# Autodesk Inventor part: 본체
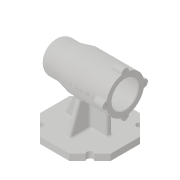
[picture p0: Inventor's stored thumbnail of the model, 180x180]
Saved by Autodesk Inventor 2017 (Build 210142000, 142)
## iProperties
Created: 2019-12
Part Number: 본체
Material: Generic
Document SubType Name: Modeling
Designer: 5-14-le
Density: 1 g/cm^3
Appearance: Default
Author: 5-14-le
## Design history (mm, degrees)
sketch "스케치2" dims "d0" = 112
  geometry: L1 (-23.196, -56)-(-56, -23.196); L2 (-56, -23.196)-(-56, 23.196); L3 (-56, 23.196)-(-23.196, 56); L4 (-23.196, 56)-(23.196, 56); L5 (23.196, 56)-(56, 23.196); L6 (56, 23.196)-(56, -23.196); L7 (56, -23.196)-(23.196, -56); L8 (23.196, -56)-(-23.196, -56); L9 (78.4, 0)-(-78.4, 0) reference; 4 further points
  constraints: 16 end point, 2 coincident, 1 midpoint, 1 parallel, 1 vertical alignment, 19 other
extrude "돌출1" new body sketch "스케치2" distance "d1" = 10; taper "d2" = 0 deg
sketch "스케치3"
  geometry: L1 (56, 23.196)-(23.196, 56) reference; L2 (-23.196, 56)-(-56, 23.196) reference; L3 (-56, -23.196)-(-23.196, -56) reference; L4 (23.196, -56)-(56, -23.196) reference; L5 (-39.598, 39.598)-(39.598, -39.598); L6 (39.598, 39.598)-(-39.598, -39.598); L7 (-78.4, 0)-(78.4, 0) reference; C1 r 5 at (-39.598, 39.598); C2 r 5 at (39.598, 39.598); C3 r 5 at (39.598, -39.598); C4 r 5 at (-39.598, -39.598); 1 further point
  constraints: 4 centre point, 4 coincident, 4 end point, 4 midpoint, 3 equal radius
  dimensions: "d3" = 10 diameter of C1
extrude "돌출2" cut sketch "스케치3" stored distance "d4" = 10; taper "d5" = 0 deg
sketch "스케치4"
  geometry: L1 (56, 80)-(-56, 80); L2 (-56, 80)-(-56, 105); L3 (56, 110)-(56, 80); L4 (56, 110)-(-11, 110); L5 (-11, 110)-(-31, 105); L6 (-31, 105)-(-56, 105); L7 (-23.196, 0)-(23.196, 0) reference; L8 (56, 0)-(56, 10) reference; L9 (56, 101)-(41, 101); L10 (41, 101)-(41, 104); L11 (41, 104)-(-13, 104); L12 (-13, 104)-(-13, 101); L13 (-13, 101)-(-25, 101); L14 (-25, 101)-(-25, 97.5); L15 (-25, 97.5)-(-43, 97.5); L16 (-43, 97.5)-(-43, 96); L17 (-43, 96)-(-47, 96); L18 (-47, 96)-(-47, 90.5); L19 (-47, 90.5)-(-50, 90.5); L20 (-50, 90.5)-(-50, 80); 1 further point
  constraints: 36 end point, 12 perpendicular, 4 point on line, 3 horizontal, 1 collinear, 1 parallel
  dimensions: "d8" = 80 distance between parallel lines of L1 L7; "d9" = 60 diameter of L4 L1; "d10" = 112 distance between parallel lines of L3 L2; "d11" = 45 distance from line of L2 L4.end; "d12" = 25 distance of L5.end L2.end; "d13" = 50 diameter of L6 L1; "d14" = 3 distance of L18.end L19.end; "d15" = 4 distance of L16.end L17.end; "d16" = 18 distance of L14.end L15.end; "d17" = 12 distance of L12.end L13.end; "d18" = 15 distance of L9.start L9.end; "d19" = 54 distance of L10.end L11.end; "d20" = 42 diameter of L9 L1; "d21" = 48 diameter of L11 L1; "d22" = 35 diameter of L15 L1; "d23" = 32 diameter of L17 L1; "d24" = 21 diameter of L19 L1
revolve "회전1" sketch "스케치4" stored, may be unused: angle "d25" = 90 deg
sketch "스케치5"
  geometry: L1 (56, 110)-(40, 110); L2 (40, 110)-(40, 116); L3 (40, 116)-(56, 116); L4 (56, 116)-(56, 110); L5 (-11, 110)-(56, 110) reference; 1 further point
  constraints: 8 end point, 2 parallel, 1 horizontal, 1 perpendicular
  dimensions: "d26" = 16 distance of L2.end L3.end; "d27" = 6 distance of L3.end L1.start
revolve "회전2" sketch "스케치5" stored, may be unused: angle "d28" = 90 deg
sketch "스케치6"
  geometry: A1 r 6 centre (0, 0) between (5.97, -0.6) and (-5.97, -0.6) reference; A2 r 6 centre (-30, -30) between (-29.4, -24.03) and (-29.4, -35.97) reference; A3 r 6 centre (0, -60) between (-5.97, -59.4) and (5.97, -59.4) reference; A4 r 6 centre (30, -30) between (29.4, -35.97) and (29.4, -24.03) reference; 5 further points
  constraints: 4 coincident
hole "구멍1" sketch "스케치6" at (-30, -30), (0, -60), (30, -30), (0, 0) diameter "d32" = 3.242; stored, may be unused: countersink angle "d36" = 90 deg, drill point angle "d38" = 118 deg; dims "d33" = 8, "d34" = 4, "d35" = 2, "d37" = 11
sketch "스케치7"
  geometry: L1 (-38, 10)-(-17.018, 54.997); L2 (-17.018, 54.997)-(31, 54.997); L3 (-43.134, 10)-(-56, 10) reference; L4 (31, 54.997)-(31, 10); L5 (31, 10)-(-38, 10); L6 (36.062, 10)-(36.062, 0) reference; L7 (-56, 0)-(-56, 10) reference; L8 (56, 0)-(56, 10) reference; L9 (23.196, 10)-(-23.196, 10) reference; 1 further point
  constraints: 8 end point, 2 perpendicular, 1 collinear, 1 parallel
  dimensions: "d39" = 115 deg angle of L3 L1; "d40" = 18 distance from line of L7 L1.start; "d41" = 25 distance between parallel lines of L8 L4; "d42" = 48.01752 distance of L1.end L2.end
extrude "돌출3" join sketch "스케치7" stored distance "d43" = 8; taper "d44" = 0 deg
sketch "스케치8"
  geometry: L1 (56.766, 18.979)-(10, 36); L2 (0, 56)-(10, 56) reference; L3 (10, 43.134)-(10, 56) reference; A1 r 30 centre (80, 0) between (50.268, -4) and (50.268, 4) reference; 1 further point
  constraints: 2 end point, 1 point on circle, 1 point on line
  dimensions: "d45" = 20 distance from line of L2 L1.end; "d46" = 110 deg angle of L3 L1
feature "리브1" sketch "스케치8" dims "d47" = 1, "d48" = 8, "d49" = 0, "d50" = 0, "d51" = 1, "d52" = 1
fillet "모깎기1" dims "d53" = 3
chamfer "모따기1" distance "d54" = 1; stored, may be unused: second distance "d55" = 2, angle "d56" = 45 deg
fillet "모깎기2" dims "d57" = 0.3
fillet "모깎기3" dims "d58" = 10
fillet "모깎기4" dims "d59" = 3
fillet "모깎기5" dims "d60" = 1
fillet "모깎기6" dims "d61" = 3
node "작업 평면1"
sketch "스케치9"
  geometry: L1 (-5.739, 83.002)-(35.739, 83.002); L2 (35.739, 83.002)-(35.739, 76.998); L3 (35.739, 76.998)-(-5.739, 76.998); L4 (-5.739, 76.998)-(-5.739, 83.002); L5 (35.739, 80)-(-5.739, 80); L6 (15, 83.002)-(15, 80); L7 (-10.631, 110)-(39, 110) reference; L8 (56, 110.171)-(56, 116) reference; 1 further point
  constraints: 4 end point, 4 midpoint, 2 other
  dimensions: "d63" = 30 distance from line of L7 L6.end; "d64" = 41 distance from line of L8 L6.end
feature "엠보싱1" sketch "스케치9" dims "d0" = 112, "d65" = 0.5, "d66" = 0
node "솔리드1"
pattern_circular "원형 패턴1" dims angle "d30" = 360 deg
mirror "미러1"
other parameters: "d62" = 30.5
